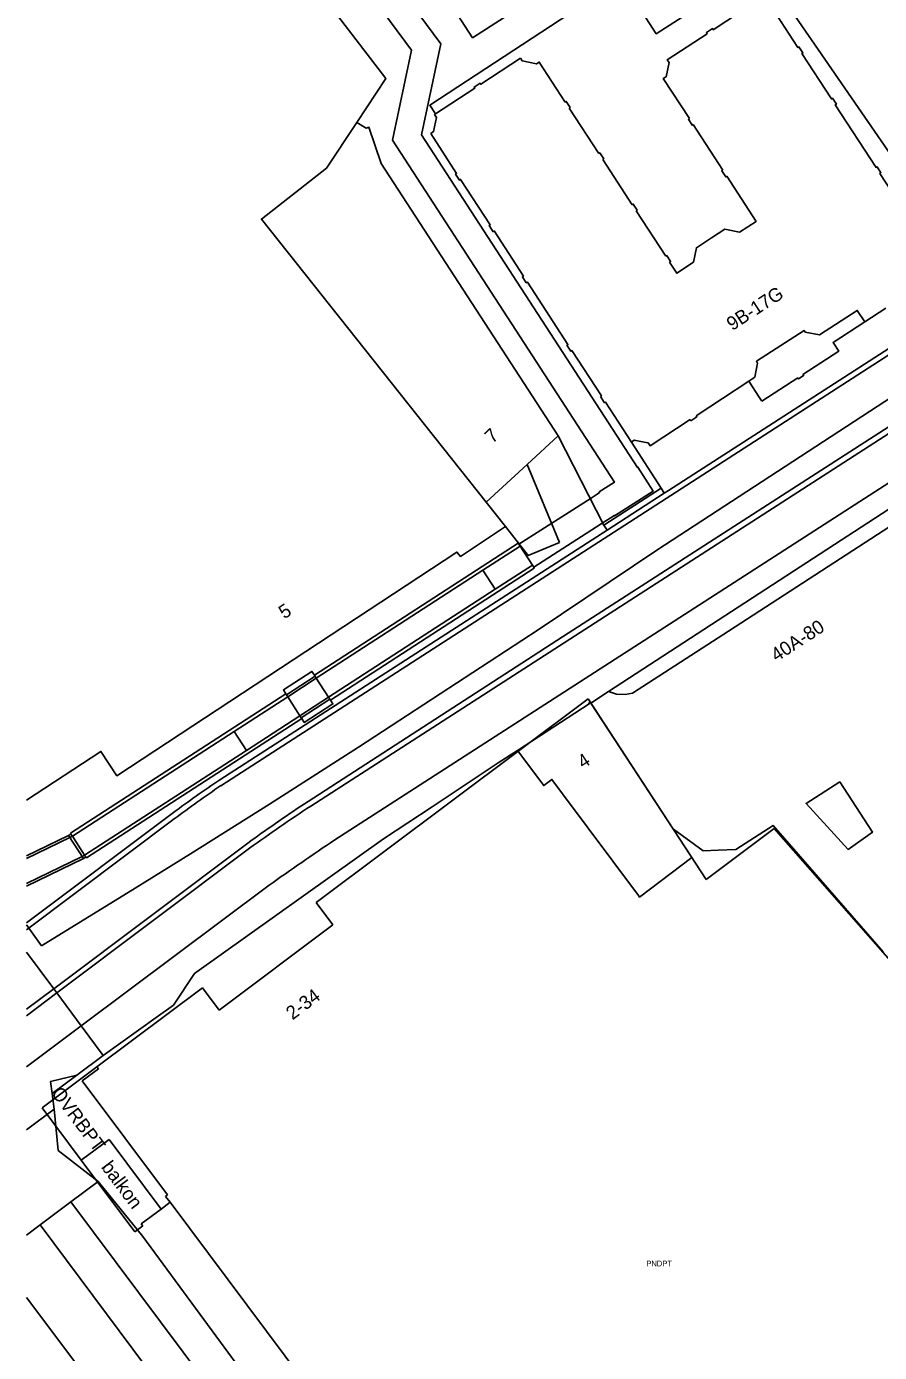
# Model space of a CAD drawing. Extents: x 194485 to 197793, y 468269 to 470822.
# Drawn here: x 194485.4 to 194560.6, y 469514.5 to 469631.3 of the extents above; entities that cross this region are included whole.
import ezdxf

# ---------------------------------------------------------------- set-up
doc = ezdxf.new("R2010")
doc.units = 0
for name, color, linetype in [('BAG plantopografie panden grensvlak pand', 7, 'Continuous'), ('BAG plantopografie panden kenmerkpunt', 7, 'Continuous'), ('BAG plantopografie panden lijnelement overig', 7, 'Continuous'), ('BAG plantopografie panden tekst opmerking', 7, 'Continuous'), ('BGT begrenzing pand op maaiveld onder overbouw', 7, 'Continuous'), ('BGT grensvlak gebouwinstallatie plus 1', 7, 'Continuous'), ('BGT grensvlak kunstwerkdeel uitbreiding populatie', 7, 'Continuous'), ('BGT grensvlak kunstwerkdeel uitbreiding populatie min 1', 7, 'Continuous'), ('BGT grensvlak overbruggingsdeel plus 1', 7, 'Continuous'), ('BGT grensvlak pand deel overbouw', 7, 'Continuous'), ('BGT grensvlak pand op maaiveld', 7, 'Continuous'), ('BGT grensvlak pand op maaiveld LR', 7, 'Continuous'), ('BGT grensvlak scheiding', 7, 'Continuous'), ('BGT grensvlak scheiding plus 1', 7, 'Continuous'), ('BGT grensvlak wegdeel', 7, 'Continuous'), ('BGT lijnelement kunstwerkdeel uitbreiding populatie duiker', 7, 'Continuous'), ('BGT tekst huisnummerreeks', 7, 'Continuous')]:
    doc.layers.add(name, color=color, linetype=linetype)

msp = doc.modelspace()

# ---------------------------------------------------------------- linework, layer by layer
at = {"layer": 'BAG plantopografie panden grensvlak pand'}
for p, q in [((194534.92, 469572.11), (194510.95, 469554.17)), ((194545.31, 469556.21), (194534.92, 469572.11)), ((194551.31, 469560.71), (194545.31, 469556.21)), ((194561.96, 469548.58), (194551.31, 469560.71)), ((194510.95, 469554.17), (194512.42, 469552.21)), ((194512.42, 469552.21), (194502.38, 469544.7)), ((194500.92, 469546.66), (194491.62, 469539.71)), ((194502.38, 469544.7), (194500.92, 469546.66)), ((194491.62, 469539.71), (194486.79, 469536.09)), ((194486.79, 469536.09), (194490.24, 469531.47)), ((194492.69, 469533.3), (194490.24, 469531.47)), ((194497.27, 469527.18), (194492.69, 469533.3)), ((194498.06, 469527.77), (194497.27, 469527.18)), ((194498.06, 469527.77), (194526.18, 469490.2))]:
    msp.add_line(p, q, dxfattribs=at)
at = {"layer": 'BAG plantopografie panden lijnelement overig'}
for p, q in [((194491.75, 469539.53), (194490.33, 469538.46)), ((194491.62, 469539.71), (194491.75, 469539.53)), ((194490.33, 469538.46), (194497.85, 469528.42)), ((194490.24, 469531.47), (194494.96, 469525.17)), ((194497.85, 469528.42), (194497.67, 469528.29)), ((194497.67, 469528.29), (194498.06, 469527.77)), ((194495.52, 469525.87), (194497.27, 469527.18)), ((194494.96, 469525.17), (194495.66, 469525.69)), ((194495.66, 469525.69), (194495.52, 469525.87))]:
    msp.add_line(p, q, dxfattribs=at)
at = {"layer": 'BGT begrenzing pand op maaiveld onder overbouw'}
for p, q in [((194549.07, 469600.09), (194549.61, 469600.44)), ((194529.53, 469592.76), (194525.93, 469589.43)), ((194525.93, 469589.43), (194527.62, 469587.29))]:
    msp.add_line(p, q, dxfattribs=at)
for points in [[(194555.31, 469604.17), (194558.63, 469606.34), (194559.28, 469605.33)], [(194549.61, 469600.44), (194549.84, 469601.69), (194549.74, 469601.85), (194551.88, 469603.24), (194553.94, 469604.57), (194554.04, 469604.42), (194555.31, 469604.17)], [(194536.7, 469572.76), (194537.42, 469572.54), (194538.16, 469572.51), (194538.82, 469572.61), (194547.27, 469578.08), (194563.67, 469588.7), (194564.32, 469588.61), (194565.36, 469587.7)]]:
    msp.add_lwpolyline(points, dxfattribs=at)
at = {"layer": 'BGT grensvlak gebouwinstallatie plus 1'}
msp.add_lwpolyline([(194549.5, 469636.24), (194540.91, 469630.7), (194535.17, 469639.6), (194542.69, 469644.45), (194545.63, 469639.89), (194546.7, 469640.59), (194549.5, 469636.24)], dxfattribs=at)
at = {"layer": 'BGT grensvlak kunstwerkdeel uitbreiding populatie'}
for p, q in [((194526.71, 469581.77), (194525.62, 469583.44)), ((194504.79, 469567.57), (194503.7, 469569.25))]:
    msp.add_line(p, q, dxfattribs=at)
for points in [[(194525.62, 469583.44), (194510.95, 469573.94), (194508.43, 469572.31), (194503.7, 469569.25)], [(194526.71, 469581.77), (194512.03, 469572.26), (194509.51, 469570.63), (194504.79, 469567.57)]]:
    msp.add_lwpolyline(points, dxfattribs=at)
at = {"layer": 'BGT grensvlak kunstwerkdeel uitbreiding populatie min 1'}
for p, q in [((194528.81, 469585.73), (194528.91, 469585.57)), ((194528.91, 469585.57), (194530, 469583.9)), ((194530, 469583.9), (194530.11, 469583.72))]:
    msp.add_line(p, q, dxfattribs=at)
for points in [[(194528.81, 469585.73), (194535.16, 469589.81), (194535.69, 469590.15), (194535.91, 469590.29), (194535.89, 469590.34), (194537.23, 469591.2), (194517.66, 469621.34), (194519.35, 469629.26), (194510.18, 469641.66), (194510.62, 469642.55), (194511.15, 469643.61)], [(194513.3, 469642.53), (194512.98, 469641.91), (194514.94, 469639.26), (194521.93, 469629.82), (194520.22, 469621.81), (194539.25, 469592.5), (194539.3, 469592.53), (194540.64, 469590.42), (194537.24, 469588.23), (194537.21, 469588.27), (194536.99, 469588.13), (194536.46, 469587.79), (194530.11, 469583.72)]]:
    msp.add_lwpolyline(points, dxfattribs=at)
at = {"layer": 'BGT grensvlak overbruggingsdeel plus 1'}
for p, q in [((194510.78, 469574.19), (194510.84, 469574.11)), ((194508.32, 469572.48), (194508.26, 469572.56)), ((194512.14, 469572.09), (194512.19, 469572.01)), ((194509.68, 469570.38), (194509.62, 469570.46)), ((194489.11, 469560.09), (194485.41, 469558.3)), ((194489.33, 469560.2), (194489.11, 469560.09)), ((194490.42, 469558.06), (194490.65, 469558.17)), ((194485.41, 469555.63), (194490.42, 469558.06))]:
    msp.add_line(p, q, dxfattribs=at)
for points in [[(194508.26, 469572.56), (194508.05, 469572.9), (194510.57, 469574.53), (194510.78, 469574.19)], [(194512.14, 469572.09), (194512.03, 469572.26), (194510.95, 469573.94), (194510.84, 469574.11)], [(194509.62, 469570.46), (194509.51, 469570.63), (194508.43, 469572.31), (194508.32, 469572.48)], [(194512.19, 469572.01), (194512.41, 469571.67), (194509.89, 469570.04), (194509.68, 469570.38)], [(194490.65, 469558.17), (194490.53, 469558.35), (194489.45, 469560.03), (194489.33, 469560.2)]]:
    msp.add_lwpolyline(points, dxfattribs=at)
at = {"layer": 'BGT grensvlak pand deel overbouw'}
for p, q in [((194553.39, 469600.4), (194550.22, 469598.33)), ((194529.53, 469592.76), (194532.38, 469585.9))]:
    msp.add_line(p, q, dxfattribs=at)
for points in [[(194553.83, 469600.69), (194557, 469602.75), (194556.5, 469603.52), (194559.28, 469605.33)], [(194553.83, 469600.69), (194553.89, 469600.59), (194553.67, 469600.45), (194553.45, 469600.3), (194553.39, 469600.4)], [(194549.07, 469600.09), (194549.99, 469598.69), (194550.22, 469598.33)], [(194536.7, 469572.76), (194565.01, 469591.19), (194566.78, 469588.64)], [(194527.62, 469587.29), (194529.63, 469584.74), (194532.38, 469585.9)]]:
    msp.add_lwpolyline(points, dxfattribs=at)
at = {"layer": 'BGT grensvlak pand op maaiveld'}
for p, q in [((194561.92, 469619.57), (194547.4, 469640.61)), ((194533.24, 469624.15), (194535.84, 469620.16)), ((194544.17, 469622.7), (194546.77, 469618.7)), ((194536.19, 469619.63), (194538.79, 469615.64)), ((194539.13, 469615.11), (194541.74, 469611.12)), ((194559.28, 469605.33), (194561.14, 469606.54)), ((194544.43, 469597.06), (194549.07, 469600.09)), ((194535.99, 469598.74), (194536.34, 469598.2)), ((194532.27, 469595.3), (194529.53, 469592.76)), ((194535.14, 469571.75), (194536.7, 469572.76)), ((194535.14, 469571.75), (194535.1, 469571.82)), ((194532.65, 469563.76), (194539.34, 469554.79)), ((194544.05, 469558.13), (194542.43, 469560.62)), ((194546.37, 469558.79), (194545.05, 469558.74)), ((194560.92, 469549.82), (194553.42, 469558.43))]:
    msp.add_line(p, q, dxfattribs=at)
for points in [[(194514.51, 469622.88), (194517.07, 469626.75), (194508.18, 469638.4)], [(194543.83, 469623.23), (194541.53, 469626.76), (194541.78, 469626.92), (194542.04, 469628.16), (194541.88, 469628.41), (194545.39, 469630.71), (194545.33, 469630.8), (194545.87, 469631.16), (194545.93, 469631.06), (194549.45, 469633.37)], [(194551.1, 469633.01), (194553.4, 469629.49), (194553.49, 469629.55), (194553.84, 469629.02), (194553.74, 469628.96), (194556.35, 469624.96), (194556.44, 469625.02), (194556.79, 469624.49), (194556.69, 469624.43), (194560.28, 469618.93), (194560.37, 469618.99), (194560.71, 469618.46), (194560.62, 469618.4), (194563.23, 469614.4), (194563.32, 469614.46), (194563.66, 469613.93), (194563.57, 469613.87), (194565.54, 469610.85)], [(194528.94, 469628.56), (194525.44, 469626.26), (194525.38, 469626.35), (194524.85, 469626), (194524.91, 469625.91), (194521.46, 469623.64)], [(194532.89, 469624.69), (194530.6, 469628.21), (194530.35, 469628.04), (194529.1, 469628.31), (194528.94, 469628.56)], [(194533.24, 469624.15), (194533.33, 469624.21), (194532.98, 469624.75), (194532.89, 469624.69)], [(194521.46, 469623.64), (194521.38, 469623.58), (194521.55, 469623.33), (194521.28, 469622.08), (194521.03, 469621.92)], [(194514.51, 469622.88), (194515.35, 469622.39), (194515.59, 469622.47), (194516.67, 469619.27), (194532.27, 469595.3)], [(194544.17, 469622.7), (194544.08, 469622.64), (194543.74, 469623.17), (194543.83, 469623.23)], [(194535.99, 469598.74), (194536.08, 469598.8), (194533.48, 469602.79), (194533.39, 469602.73), (194533.04, 469603.27), (194533.13, 469603.33), (194529.55, 469608.83), (194529.46, 469608.77), (194529.11, 469609.3), (194529.2, 469609.36), (194526.62, 469613.33), (194526.53, 469613.27), (194526.18, 469613.8), (194526.27, 469613.86), (194523.67, 469617.87), (194523.57, 469617.81), (194523.23, 469618.34), (194523.32, 469618.4), (194521.03, 469621.92)], [(194536.19, 469619.63), (194536.28, 469619.69), (194535.93, 469620.22), (194535.84, 469620.16)], [(194547.12, 469618.16), (194547.03, 469618.1), (194546.68, 469618.64), (194546.77, 469618.7)], [(194547.12, 469618.16), (194549.71, 469614.18), (194548.24, 469613.22)], [(194539.13, 469615.11), (194539.23, 469615.17), (194538.88, 469615.7), (194538.79, 469615.64)], [(194544.18, 469610.57), (194544.45, 469611.86), (194545.79, 469612.74), (194546.94, 469613.49), (194548.24, 469613.22)], [(194542.09, 469610.58), (194542.18, 469610.64), (194541.83, 469611.17), (194541.74, 469611.12)], [(194544.18, 469610.57), (194542.72, 469609.61), (194542.09, 469610.58)], [(194536.34, 469598.2), (194536.43, 469598.26), (194538.72, 469594.74)], [(194538.72, 469594.74), (194538.97, 469594.91), (194539.85, 469594.73), (194540.21, 469594.66), (194540.37, 469594.41), (194543.9, 469596.72)], [(194544.43, 469597.06), (194544.49, 469596.97), (194543.96, 469596.62), (194543.9, 469596.72)], [(194485.41, 469563.19), (194491.97, 469567.49), (194493.38, 469565.35), (194523.35, 469585.05), (194523.65, 469584.67), (194527.62, 469587.29)], [(194535.1, 469571.82), (194534.96, 469571.73), (194535, 469571.67), (194528.68, 469567.58)], [(194528.68, 469567.58), (194530.99, 469564.48), (194531.71, 469565.02), (194532.65, 469563.76)], [(194557.09, 469564.81), (194559.96, 469560.37), (194557.82, 469558.85), (194554.12, 469562.91), (194557.09, 469564.81)], [(194545.05, 469558.74), (194542.44, 469560.63), (194542.43, 469560.62)], [(194553.42, 469558.43), (194551.2, 469560.97), (194547.93, 469558.84), (194546.37, 469558.79)], [(194539.34, 469554.79), (194539.44, 469554.66), (194544.05, 469558.13)]]:
    msp.add_lwpolyline(points, dxfattribs=at)
at = {"layer": 'BGT grensvlak pand op maaiveld LR'}
msp.add_line((194542.43, 469560.62), (194535.14, 469571.75), dxfattribs=at)
msp.add_lwpolyline([(194525.93, 469589.43), (194506.12, 469614.38), (194511.86, 469618.87), (194514.51, 469622.88)], dxfattribs=at)
at = {"layer": 'BGT grensvlak scheiding'}
for p, q in [((194528.91, 469585.57), (194525.62, 469583.44)), ((194530, 469583.9), (194526.71, 469581.77)), ((194508.32, 469572.48), (194510.84, 469574.11)), ((194489.29, 469560.28), (194508.26, 469572.56)), ((194509.62, 469570.46), (194512.14, 469572.09)), ((194509.68, 469570.38), (194490.7, 469558.1)), ((194489.33, 469560.2), (194489.29, 469560.28)), ((194490.7, 469558.1), (194490.65, 469558.17))]:
    msp.add_line(p, q, dxfattribs=at)
for points in [[(194510.78, 469574.19), (194528.75, 469585.82), (194528.81, 469585.73)], [(194512.19, 469572.01), (194530.16, 469583.64), (194530.11, 469583.72)], [(194503.7, 469569.25), (194489.45, 469560.03), (194489.22, 469559.92), (194485.41, 469558.07)], [(194504.79, 469567.57), (194490.53, 469558.35), (194490.31, 469558.24), (194485.41, 469555.86)]]:
    msp.add_lwpolyline(points, dxfattribs=at)
at = {"layer": 'BGT grensvlak scheiding plus 1'}
msp.add_line((194490.42, 469558.06), (194489.11, 469560.09), dxfattribs=at)
at = {"layer": 'BGT grensvlak wegdeel'}
for p, q in [((194605.26, 469630.73), (194502.54, 469564.47)), ((194590.64, 469621.85), (194541.98, 469590.47)), ((194510.46, 469562.67), (194600.02, 469620.4)), ((194602.05, 469617.37), (194512.58, 469559.69)), ((194532.27, 469595.3), (194536.29, 469587.43)), ((194541.33, 469590.68), (194538.72, 469594.74)), ((194541.33, 469590.68), (194536.29, 469587.43)), ((194536.58, 469586.99), (194541.62, 469590.24)), ((194541.62, 469590.24), (194541.33, 469590.68)), ((194541.62, 469590.24), (194541.98, 469590.47)), ((194536.29, 469587.43), (194536.58, 469586.99)), ((194502.45, 469564.98), (194536.58, 469586.99)), ((194526.99, 469566.47), (194528.68, 469567.58)), ((194521.17, 469562.62), (194526.99, 469566.47)), ((194485.41, 469552.38), (194498.36, 469562.1)), ((194516.87, 469559.78), (194521.17, 469562.62)), ((194498.43, 469561.55), (194485.41, 469551.77)), ((194487.81, 469546.58), (194505.14, 469559.57)), ((194488.08, 469546.21), (194505.07, 469558.96)), ((194506.79, 469555.71), (194490.24, 469543.31)), ((194487.81, 469546.58), (194485.41, 469549.8)), ((194485.41, 469544.79), (194487.81, 469546.58)), ((194488.08, 469546.21), (194487.81, 469546.58)), ((194485.41, 469544.21), (194488.08, 469546.21)), ((194490.24, 469543.31), (194488.08, 469546.21)), ((194498.38, 469545.14), (194496.84, 469544.04)), ((194490.24, 469543.31), (194485.41, 469539.69)), ((194490.24, 469543.31), (194492.18, 469540.7)), ((194496.84, 469544.04), (194492.18, 469540.7)), ((194492.18, 469540.7), (194489.85, 469538.97)), ((194489.85, 469538.97), (194487.67, 469537.35)), ((194487.67, 469537.35), (194487.84, 469535.97)), ((194485.41, 469534.16), (194487.84, 469535.97)), ((194491.72, 469529.6), (194489.33, 469527.8)), ((194486.62, 469525.78), (194489.33, 469527.8)), ((194489.33, 469527.8), (194546.18, 469451.79)), ((194485.41, 469524.87), (194486.62, 469525.78))]:
    msp.add_line(p, q, dxfattribs=at)
for points in [[(194523.72, 469641.5), (194519.38, 469638.61), (194524.73, 469630.35), (194529.15, 469633.18)], [(194538.81, 469642.1), (194540.11, 469640.12), (194536.9, 469638), (194538.84, 469635.04), (194534.56, 469632.22), (194534.05, 469633), (194520.95, 469624.41), (194521.46, 469623.64)], [(194510.23, 469563.09), (194533.15, 469577.89), (194608.12, 469626.15)], [(194516.87, 469559.78), (194500.21, 469547.93), (194498.38, 469545.14)], [(194489.85, 469538.97), (194487.53, 469538.42), (194487.67, 469537.35)], [(194487.84, 469535.97), (194488.21, 469532.34), (194491.72, 469529.6)], [(194491.72, 469529.6), (194495.66, 469524.77), (194514.32, 469499.38), (194525.12, 469485.09), (194541.55, 469463.19)], [(194486.62, 469525.78), (194527.36, 469471.14), (194560.25, 469427.17)], [(194485.41, 469519.38), (194508.02, 469489.28), (194532.51, 469456.6), (194552.3, 469430.08)]]:
    msp.add_lwpolyline(points, dxfattribs=at)
for centre, radius, start, end in [((194554.94, 469486.09), 94.76, 123.639, 126.6641), ((194571.22, 469463.8), 121.87, 124.3004, 126.6719), ((194590.17, 469442), 145.1, 123.4331, 125.8776), ((194601.67, 469424.45), 165.61, 123.4203, 125.6842), ((194639.19, 469369.75), 228.27, 123.688, 125.4517)]:
    msp.add_arc(centre, radius, start, end, dxfattribs=at)
at = {"layer": 'BGT lijnelement kunstwerkdeel uitbreiding populatie duiker'}
msp.add_line((194485.41, 469552.2), (194486.74, 469550.35), dxfattribs=at)
for points in [[(194540.95, 469585.21), (194549.58, 469590.81), (194561.73, 469598.74), (194570.16, 469604.37), (194577.33, 469609.24), (194586.33, 469615.41), (194599.24, 469624.48), (194608.3, 469630.96), (194619.41, 469638.97)], [(194486.74, 469550.35), (194495, 469555.45), (194499.85, 469558.46), (194506.84, 469562.84), (194514.68, 469567.85), (194530.5, 469578.19), (194540.95, 469585.21)]]:
    msp.add_lwpolyline(points, dxfattribs=at)

# ---------------------------------------------------------------- texts
at = {"layer": 'BAG plantopografie panden kenmerkpunt'}
msp.add_text('PNDPT', height=0.5, dxfattribs=at).set_placement((194540.03, 469522.13))
at = {"layer": 'BAG plantopografie panden tekst opmerking'}
for s, rotation, p in [('2-34', 36.8126, (194508.85, 469543.79)), ('OVRBPT', 306.8126, (194487.54, 469537.38)), ('balkon', 306.8126, (194491.94, 469530.86))]:
    msp.add_text(s, height=1.2, rotation=rotation, dxfattribs=at).set_placement(p)
at = {"layer": 'BGT tekst huisnummerreeks'}
for s, rotation, p in [('9B-17G', 33, (194547.61, 469604.51)), ('7', 42.8, (194526.48, 469594.57)), ('5', 33.3, (194508.13, 469579.11)), ('40A-80', 32.9, (194551.51, 469575.35)), ('4', 33, (194534.46, 469565.92))]:
    msp.add_text(s, height=1.2, rotation=rotation, dxfattribs=at).set_placement(p)

doc.saveas('drawing.dxf')
